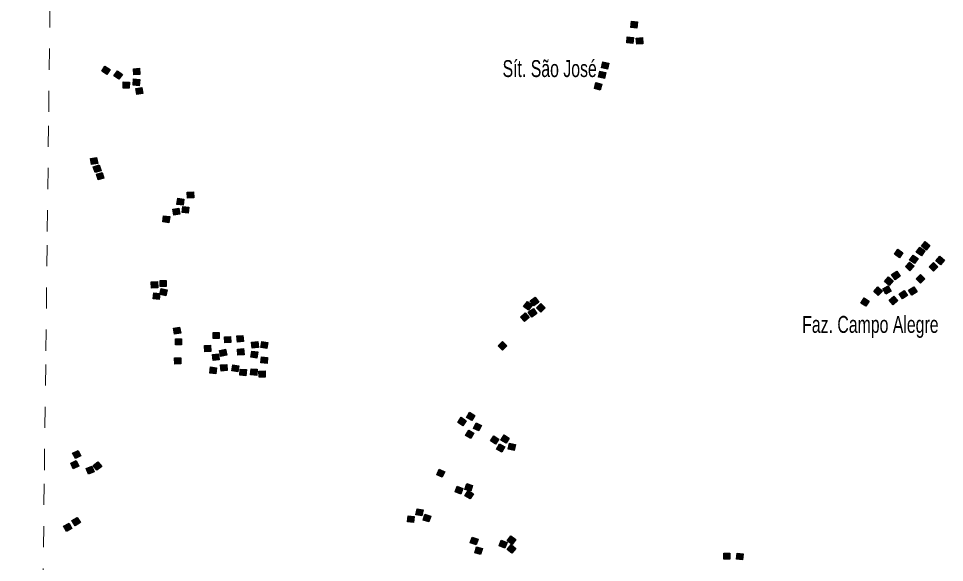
# Model space of a CAD drawing. Extents: x 679 to 705, y 7427.4 to 7455.4.
# Drawn here: x 679.037 to 683.416, y 7437.424 to 7439.999 of the extents above; entities that cross this region are included whole.
import ezdxf

# ---------------------------------------------------------------- set-up
doc = ezdxf.new("R2010")
doc.units = 0
doc.header["$LTSCALE"] = 0.032
doc.linetypes.add('SHORT_DASHED', pattern=[2.7, 1.5, -1.2])
doc.layers.add('2', color=7, linetype='Continuous', lineweight=25)
doc.layers.add('58', color=7, linetype='SHORT_DASHED', lineweight=13)
doc.layers.add('61', color=7, linetype='Continuous')

msp = doc.modelspace()

# ---------------------------------------------------------------- hatches: boundary and pattern name
at = {"layer": '2'}
for points in [[(681.9643, 7439.9827), (681.9609, 7439.9539), (681.9321, 7439.9572), (681.9355, 7439.986)], [(681.9448, 7439.9097), (681.9423, 7439.8808), (681.9134, 7439.8833), (681.9159, 7439.9122)], [(681.9873, 7439.9087), (681.9893, 7439.8797), (681.9604, 7439.8777), (681.9583, 7439.9066)], [(681.8286, 7439.7877), (681.8217, 7439.7595), (681.7935, 7439.7664), (681.8004, 7439.7945)], [(679.4463, 7439.7739), (679.4707, 7439.7582), (679.455, 7439.7338), (679.4306, 7439.7495)], [(679.5049, 7439.7518), (679.5283, 7439.7347), (679.5111, 7439.7113), (679.4877, 7439.7284)], [(679.61, 7439.7633), (679.6118, 7439.7344), (679.5828, 7439.7327), (679.5811, 7439.7616)], [(681.8141, 7439.7432), (681.8076, 7439.715), (681.7793, 7439.7214), (681.7858, 7439.7497)], [(679.5618, 7439.6984), (679.5611, 7439.6694), (679.5321, 7439.6701), (679.5328, 7439.6991)], [(679.6107, 7439.71), (679.6077, 7439.6812), (679.5788, 7439.6842), (679.5818, 7439.713)], [(681.7951, 7439.6888), (681.7883, 7439.6606), (681.7601, 7439.6674), (681.7669, 7439.6956)], [(679.6205, 7439.6731), (679.625, 7439.6444), (679.5964, 7439.6399), (679.5918, 7439.6686)], [(679.4064, 7439.3415), (679.4117, 7439.313), (679.3832, 7439.3077), (679.3779, 7439.3362)], [(679.4184, 7439.3062), (679.4276, 7439.2786), (679.4001, 7439.2695), (679.3909, 7439.297)], [(679.4337, 7439.2706), (679.4414, 7439.2427), (679.4135, 7439.2349), (679.4057, 7439.2628)], [(679.8645, 7439.1788), (679.8659, 7439.1498), (679.8369, 7439.1484), (679.8355, 7439.1774)], [(679.8189, 7439.1445), (679.8154, 7439.1157), (679.7866, 7439.1192), (679.7901, 7439.148)], [(679.7959, 7439.1019), (679.8004, 7439.0732), (679.7717, 7439.0688), (679.7672, 7439.0974)], [(679.8427, 7439.1064), (679.8395, 7439.0776), (679.8107, 7439.0808), (679.8139, 7439.1096)], [(679.7522, 7439.0613), (679.7482, 7439.0326), (679.7194, 7439.0366), (679.7234, 7439.0653)], [(683.2993, 7438.9164), (683.323, 7438.8997), (683.3064, 7438.876), (683.2826, 7438.8927)], [(683.3246, 7438.9437), (683.3471, 7438.9253), (683.3287, 7438.9029), (683.3063, 7438.9213)], [(683.1958, 7438.9068), (683.2194, 7438.89), (683.2026, 7438.8664), (683.179, 7438.8832)], [(683.2675, 7438.8797), (683.2912, 7438.863), (683.2744, 7438.8393), (683.2507, 7438.856)], [(683.3937, 7438.8736), (683.4157, 7438.8546), (683.3967, 7438.8327), (683.3748, 7438.8516)], [(683.251, 7438.8465), (683.2722, 7438.8267), (683.2524, 7438.8055), (683.2312, 7438.8253)], [(683.3632, 7438.8449), (683.3837, 7438.8244), (683.3632, 7438.8039), (683.3427, 7438.8244)], [(683.151, 7438.7762), (683.1733, 7438.7576), (683.1547, 7438.7354), (683.1325, 7438.7539)], [(683.1898, 7438.8032), (683.2062, 7438.7793), (683.1823, 7438.7628), (683.1659, 7438.7867)], [(683.3027, 7438.7875), (683.3232, 7438.767), (683.3026, 7438.7465), (683.2821, 7438.767)], [(679.694, 7438.754), (679.6955, 7438.725), (679.6665, 7438.7235), (679.6651, 7438.7525)], [(679.7362, 7438.7597), (679.7362, 7438.7307), (679.7072, 7438.7307), (679.7072, 7438.7597)], [(683.15, 7438.7342), (683.1643, 7438.709), (683.1391, 7438.6947), (683.1247, 7438.7199)], [(679.7058, 7438.6974), (679.7025, 7438.6686), (679.6737, 7438.6719), (679.677, 7438.7007)], [(679.7405, 7438.7149), (679.7341, 7438.6866), (679.7058, 7438.693), (679.7123, 7438.7213)], [(683.101, 7438.7284), (683.1223, 7438.7087), (683.1025, 7438.6874), (683.0813, 7438.7072)], [(683.225, 7438.7122), (683.2413, 7438.6882), (683.2173, 7438.6719), (683.201, 7438.6959)], [(683.27, 7438.7297), (683.2858, 7438.7054), (683.2615, 7438.6896), (683.2457, 7438.7138)], [(681.4434, 7438.6597), (681.4663, 7438.642), (681.4487, 7438.619), (681.4257, 7438.6367)], [(681.4806, 7438.6804), (681.4979, 7438.6571), (681.4745, 7438.6399), (681.4573, 7438.6632)], [(681.5065, 7438.6503), (681.527, 7438.6298), (681.5064, 7438.6093), (681.4859, 7438.6298)], [(683.0352, 7438.6768), (683.0598, 7438.6615), (683.0444, 7438.6369), (683.0198, 7438.6523)], [(683.1762, 7438.6854), (683.1955, 7438.6637), (683.1738, 7438.6444), (683.1546, 7438.6661)], [(681.4325, 7438.6056), (681.4519, 7438.584), (681.4304, 7438.5646), (681.411, 7438.5862)], [(681.4718, 7438.6261), (681.4881, 7438.6021), (681.4642, 7438.5858), (681.4478, 7438.6097)], [(679.7988, 7438.5385), (679.8041, 7438.51), (679.7756, 7438.5047), (679.7703, 7438.5333)], [(679.9863, 7438.5128), (679.9863, 7438.4838), (679.9573, 7438.4838), (679.9573, 7438.5128)], [(679.808, 7438.4837), (679.808, 7438.4547), (679.779, 7438.4547), (679.779, 7438.4837)], [(680.0401, 7438.4938), (680.0414, 7438.4649), (680.0124, 7438.4635), (680.0111, 7438.4925)], [(680.0984, 7438.4992), (680.101, 7438.4703), (680.0722, 7438.4677), (680.0695, 7438.4966)], [(680.1685, 7438.4707), (680.1717, 7438.4419), (680.1428, 7438.4387), (680.1396, 7438.4675)], [(680.2168, 7438.4653), (680.2121, 7438.4367), (680.1835, 7438.4415), (680.1882, 7438.4701)], [(681.3265, 7438.47), (681.3468, 7438.4493), (681.326, 7438.429), (681.3058, 7438.4497)], [(679.9459, 7438.4524), (679.9474, 7438.4235), (679.9185, 7438.422), (679.917, 7438.4509)], [(680.0167, 7438.4336), (680.023, 7438.4053), (679.9947, 7438.399), (679.9884, 7438.4273)], [(680.1019, 7438.4367), (680.104, 7438.4078), (680.075, 7438.4057), (680.073, 7438.4347)], [(679.8045, 7438.3929), (679.805, 7438.3639), (679.776, 7438.3635), (679.7755, 7438.3925)], [(679.9831, 7438.4127), (679.9863, 7438.3839), (679.9575, 7438.3806), (679.9543, 7438.4095)], [(680.1686, 7438.4209), (680.1643, 7438.3922), (680.1356, 7438.3965), (680.1399, 7438.4252)], [(680.2152, 7438.3953), (680.2127, 7438.3664), (680.1838, 7438.3689), (680.1863, 7438.3978)], [(679.9738, 7438.3463), (679.9702, 7438.3175), (679.9414, 7438.3211), (679.945, 7438.3499)], [(680.0221, 7438.3618), (680.0243, 7438.3329), (679.9954, 7438.3307), (679.9932, 7438.3596)], [(680.0795, 7438.3552), (680.0748, 7438.3266), (680.0461, 7438.3314), (680.0509, 7438.36)], [(680.115, 7438.3375), (680.113, 7438.3086), (680.0841, 7438.3106), (680.0861, 7438.3395)], [(680.1659, 7438.3389), (680.1638, 7438.3099), (680.1349, 7438.312), (680.1369, 7438.3409)], [(680.203, 7438.3309), (680.2038, 7438.3019), (680.1748, 7438.3011), (680.174, 7438.3301)], [(681.1704, 7438.1354), (681.1954, 7438.1207), (681.1808, 7438.0957), (681.1557, 7438.1103)], [(681.1302, 7438.1117), (681.1542, 7438.0955), (681.1379, 7438.0715), (681.1139, 7438.0877)], [(681.2006, 7438.0854), (681.2268, 7438.0731), (681.2145, 7438.0468), (681.1883, 7438.0591)], [(681.166, 7438.0509), (681.1907, 7438.0357), (681.1755, 7438.011), (681.1508, 7438.0262)], [(681.2848, 7438.024), (681.3088, 7438.0078), (681.2926, 7437.9837), (681.2686, 7438)], [(681.3334, 7438.0286), (681.3581, 7438.0134), (681.343, 7437.9887), (681.3182, 7438.0038)], [(681.3594, 7437.9893), (681.3877, 7437.983), (681.3814, 7437.9547), (681.3531, 7437.961)], [(679.319, 7437.955), (679.3325, 7437.9293), (679.3069, 7437.9158), (679.2934, 7437.9415)], [(681.312, 7437.9853), (681.3372, 7437.9711), (681.323, 7437.9458), (681.2977, 7437.9601)], [(679.3106, 7437.9067), (679.3225, 7437.8803), (679.296, 7437.8684), (679.2842, 7437.8949)], [(679.4129, 7437.9014), (679.4307, 7437.8785), (679.4078, 7437.8607), (679.39, 7437.8836)], [(679.3845, 7437.881), (679.3956, 7437.8542), (679.3688, 7437.8431), (679.3577, 7437.8699)], [(681.0533, 7437.8541), (681.0413, 7437.8277), (681.0149, 7437.8397), (681.0269, 7437.8661)], [(681.139, 7437.7752), (681.1283, 7437.7483), (681.1013, 7437.759), (681.1121, 7437.786)], [(681.1846, 7437.7893), (681.1759, 7437.7616), (681.1483, 7437.7703), (681.157, 7437.798)], [(681.188, 7437.7496), (681.1726, 7437.725), (681.148, 7437.7404), (681.1634, 7437.765)], [(679.3146, 7437.6378), (679.3297, 7437.6131), (679.305, 7437.598), (679.2899, 7437.6227)], [(680.9086, 7437.6421), (680.9047, 7437.6133), (680.876, 7437.6172), (680.8798, 7437.6459)], [(680.9507, 7437.6731), (680.9452, 7437.6446), (680.9167, 7437.6501), (680.9222, 7437.6785)], [(680.9869, 7437.6441), (680.9783, 7437.6164), (680.9506, 7437.6251), (680.9592, 7437.6528)], [(679.2761, 7437.6103), (679.2894, 7437.5846), (679.2637, 7437.5713), (679.2503, 7437.597)], [(681.3648, 7437.5503), (681.3886, 7437.5338), (681.372, 7437.51), (681.3482, 7437.5265)], [(681.2104, 7437.535), (681.2008, 7437.5077), (681.1735, 7437.5173), (681.1831, 7437.5446)], [(681.3202, 7437.5296), (681.3474, 7437.5197), (681.3375, 7437.4924), (681.3103, 7437.5024)], [(681.3661, 7437.5091), (681.3887, 7437.4909), (681.3706, 7437.4683), (681.3479, 7437.4864)], [(681.2026, 7437.4987), (681.2305, 7437.4907), (681.2225, 7437.4628), (681.1946, 7437.4708)], [(682.4007, 7437.4686), (682.4007, 7437.4396), (682.3717, 7437.4396), (682.3717, 7437.4686)], [(682.4645, 7437.4653), (682.461, 7437.4365), (682.4322, 7437.44), (682.4357, 7437.4688)]]:
    msp.add_hatch(color=256, dxfattribs=at).paths.add_polyline_path(points)

# ---------------------------------------------------------------- linework, layer by layer
for points in [[(681.9643, 7439.9827), (681.9609, 7439.9539), (681.9321, 7439.9572), (681.9355, 7439.986)], [(681.9448, 7439.9097), (681.9423, 7439.8808), (681.9134, 7439.8833), (681.9159, 7439.9122)], [(681.9873, 7439.9087), (681.9893, 7439.8797), (681.9604, 7439.8777), (681.9583, 7439.9066)], [(681.8286, 7439.7877), (681.8217, 7439.7595), (681.7935, 7439.7664), (681.8004, 7439.7945)], [(679.4463, 7439.7739), (679.4707, 7439.7582), (679.455, 7439.7338), (679.4306, 7439.7495)], [(679.5049, 7439.7518), (679.5283, 7439.7347), (679.5111, 7439.7113), (679.4877, 7439.7284)], [(679.61, 7439.7633), (679.6118, 7439.7344), (679.5828, 7439.7327), (679.5811, 7439.7616)], [(681.8141, 7439.7432), (681.8076, 7439.715), (681.7793, 7439.7214), (681.7858, 7439.7497)], [(679.5618, 7439.6984), (679.5611, 7439.6694), (679.5321, 7439.6701), (679.5328, 7439.6991)], [(679.6107, 7439.71), (679.6077, 7439.6812), (679.5788, 7439.6842), (679.5818, 7439.713)], [(681.7951, 7439.6888), (681.7883, 7439.6606), (681.7601, 7439.6674), (681.7669, 7439.6956)], [(679.6205, 7439.6731), (679.625, 7439.6444), (679.5964, 7439.6399), (679.5918, 7439.6686)], [(679.4064, 7439.3415), (679.4117, 7439.313), (679.3832, 7439.3077), (679.3779, 7439.3362)], [(679.4184, 7439.3062), (679.4276, 7439.2786), (679.4001, 7439.2695), (679.3909, 7439.297)], [(679.4337, 7439.2706), (679.4414, 7439.2427), (679.4135, 7439.2349), (679.4057, 7439.2628)], [(679.8645, 7439.1788), (679.8659, 7439.1498), (679.8369, 7439.1484), (679.8355, 7439.1774)], [(679.8189, 7439.1445), (679.8154, 7439.1157), (679.7866, 7439.1192), (679.7901, 7439.148)], [(679.7959, 7439.1019), (679.8004, 7439.0732), (679.7717, 7439.0688), (679.7672, 7439.0974)], [(679.8427, 7439.1064), (679.8395, 7439.0776), (679.8107, 7439.0808), (679.8139, 7439.1096)], [(679.7522, 7439.0613), (679.7482, 7439.0326), (679.7194, 7439.0366), (679.7234, 7439.0653)], [(683.2993, 7438.9164), (683.323, 7438.8997), (683.3064, 7438.876), (683.2826, 7438.8927)], [(683.3246, 7438.9437), (683.3471, 7438.9253), (683.3287, 7438.9029), (683.3063, 7438.9213)], [(683.1958, 7438.9068), (683.2194, 7438.89), (683.2026, 7438.8664), (683.179, 7438.8832)], [(683.2675, 7438.8797), (683.2912, 7438.863), (683.2744, 7438.8393), (683.2507, 7438.856)], [(683.3937, 7438.8736), (683.4157, 7438.8546), (683.3967, 7438.8327), (683.3748, 7438.8516)], [(683.251, 7438.8465), (683.2722, 7438.8267), (683.2524, 7438.8055), (683.2312, 7438.8253)], [(683.3632, 7438.8449), (683.3837, 7438.8244), (683.3632, 7438.8039), (683.3427, 7438.8244)], [(683.151, 7438.7762), (683.1733, 7438.7576), (683.1547, 7438.7354), (683.1325, 7438.7539)], [(683.1898, 7438.8032), (683.2062, 7438.7793), (683.1823, 7438.7628), (683.1659, 7438.7867)], [(683.3027, 7438.7875), (683.3232, 7438.767), (683.3026, 7438.7465), (683.2821, 7438.767)], [(679.694, 7438.754), (679.6955, 7438.725), (679.6665, 7438.7235), (679.6651, 7438.7525)], [(679.7362, 7438.7597), (679.7362, 7438.7307), (679.7072, 7438.7307), (679.7072, 7438.7597)], [(683.15, 7438.7342), (683.1643, 7438.709), (683.1391, 7438.6947), (683.1247, 7438.7199)], [(679.7058, 7438.6974), (679.7025, 7438.6686), (679.6737, 7438.6719), (679.677, 7438.7007)], [(679.7405, 7438.7149), (679.7341, 7438.6866), (679.7058, 7438.693), (679.7123, 7438.7213)], [(683.101, 7438.7284), (683.1223, 7438.7087), (683.1025, 7438.6874), (683.0813, 7438.7072)], [(683.225, 7438.7122), (683.2413, 7438.6882), (683.2173, 7438.6719), (683.201, 7438.6959)], [(683.27, 7438.7297), (683.2858, 7438.7054), (683.2615, 7438.6896), (683.2457, 7438.7138)], [(681.4434, 7438.6597), (681.4663, 7438.642), (681.4487, 7438.619), (681.4257, 7438.6367)], [(681.4806, 7438.6804), (681.4979, 7438.6571), (681.4745, 7438.6399), (681.4573, 7438.6632)], [(681.5065, 7438.6503), (681.527, 7438.6298), (681.5064, 7438.6093), (681.4859, 7438.6298)], [(683.0352, 7438.6768), (683.0598, 7438.6615), (683.0444, 7438.6369), (683.0198, 7438.6523)], [(683.1762, 7438.6854), (683.1955, 7438.6637), (683.1738, 7438.6444), (683.1546, 7438.6661)], [(681.4325, 7438.6056), (681.4519, 7438.584), (681.4304, 7438.5646), (681.411, 7438.5862)], [(681.4718, 7438.6261), (681.4881, 7438.6021), (681.4642, 7438.5858), (681.4478, 7438.6097)], [(679.7988, 7438.5385), (679.8041, 7438.51), (679.7756, 7438.5047), (679.7703, 7438.5333)], [(679.9863, 7438.5128), (679.9863, 7438.4838), (679.9573, 7438.4838), (679.9573, 7438.5128)], [(679.808, 7438.4837), (679.808, 7438.4547), (679.779, 7438.4547), (679.779, 7438.4837)], [(680.0401, 7438.4938), (680.0414, 7438.4649), (680.0124, 7438.4635), (680.0111, 7438.4925)], [(680.0984, 7438.4992), (680.101, 7438.4703), (680.0722, 7438.4677), (680.0695, 7438.4966)], [(680.1685, 7438.4707), (680.1717, 7438.4419), (680.1428, 7438.4387), (680.1396, 7438.4675)], [(680.2168, 7438.4653), (680.2121, 7438.4367), (680.1835, 7438.4415), (680.1882, 7438.4701)], [(681.3265, 7438.47), (681.3468, 7438.4493), (681.326, 7438.429), (681.3058, 7438.4497)], [(679.9459, 7438.4524), (679.9474, 7438.4235), (679.9185, 7438.422), (679.917, 7438.4509)], [(680.0167, 7438.4336), (680.023, 7438.4053), (679.9947, 7438.399), (679.9884, 7438.4273)], [(680.1019, 7438.4367), (680.104, 7438.4078), (680.075, 7438.4057), (680.073, 7438.4347)], [(679.8045, 7438.3929), (679.805, 7438.3639), (679.776, 7438.3635), (679.7755, 7438.3925)], [(679.9831, 7438.4127), (679.9863, 7438.3839), (679.9575, 7438.3806), (679.9543, 7438.4095)], [(680.1686, 7438.4209), (680.1643, 7438.3922), (680.1356, 7438.3965), (680.1399, 7438.4252)], [(680.2152, 7438.3953), (680.2127, 7438.3664), (680.1838, 7438.3689), (680.1863, 7438.3978)], [(679.9738, 7438.3463), (679.9702, 7438.3175), (679.9414, 7438.3211), (679.945, 7438.3499)], [(680.0221, 7438.3618), (680.0243, 7438.3329), (679.9954, 7438.3307), (679.9932, 7438.3596)], [(680.0795, 7438.3552), (680.0748, 7438.3266), (680.0461, 7438.3314), (680.0509, 7438.36)], [(680.115, 7438.3375), (680.113, 7438.3086), (680.0841, 7438.3106), (680.0861, 7438.3395)], [(680.1659, 7438.3389), (680.1638, 7438.3099), (680.1349, 7438.312), (680.1369, 7438.3409)], [(680.203, 7438.3309), (680.2038, 7438.3019), (680.1748, 7438.3011), (680.174, 7438.3301)], [(681.1704, 7438.1354), (681.1954, 7438.1207), (681.1808, 7438.0957), (681.1557, 7438.1103)], [(681.1302, 7438.1117), (681.1542, 7438.0955), (681.1379, 7438.0715), (681.1139, 7438.0877)], [(681.2006, 7438.0854), (681.2268, 7438.0731), (681.2145, 7438.0468), (681.1883, 7438.0591)], [(681.166, 7438.0509), (681.1907, 7438.0357), (681.1755, 7438.011), (681.1508, 7438.0262)], [(681.2848, 7438.024), (681.3088, 7438.0078), (681.2926, 7437.9837), (681.2686, 7438)], [(681.3334, 7438.0286), (681.3581, 7438.0134), (681.343, 7437.9887), (681.3182, 7438.0038)], [(681.3594, 7437.9893), (681.3877, 7437.983), (681.3814, 7437.9547), (681.3531, 7437.961)], [(679.319, 7437.955), (679.3325, 7437.9293), (679.3069, 7437.9158), (679.2934, 7437.9415)], [(681.312, 7437.9853), (681.3372, 7437.9711), (681.323, 7437.9458), (681.2977, 7437.9601)], [(679.3106, 7437.9067), (679.3225, 7437.8803), (679.296, 7437.8684), (679.2842, 7437.8949)], [(679.4129, 7437.9014), (679.4307, 7437.8785), (679.4078, 7437.8607), (679.39, 7437.8836)], [(679.3845, 7437.881), (679.3956, 7437.8542), (679.3688, 7437.8431), (679.3577, 7437.8699)], [(681.0533, 7437.8541), (681.0413, 7437.8277), (681.0149, 7437.8397), (681.0269, 7437.8661)], [(681.139, 7437.7752), (681.1283, 7437.7483), (681.1013, 7437.759), (681.1121, 7437.786)], [(681.1846, 7437.7893), (681.1759, 7437.7616), (681.1483, 7437.7703), (681.157, 7437.798)], [(681.188, 7437.7496), (681.1726, 7437.725), (681.148, 7437.7404), (681.1634, 7437.765)], [(679.3146, 7437.6378), (679.3297, 7437.6131), (679.305, 7437.598), (679.2899, 7437.6227)], [(680.9086, 7437.6421), (680.9047, 7437.6133), (680.876, 7437.6172), (680.8798, 7437.6459)], [(680.9507, 7437.6731), (680.9452, 7437.6446), (680.9167, 7437.6501), (680.9222, 7437.6785)], [(680.9869, 7437.6441), (680.9783, 7437.6164), (680.9506, 7437.6251), (680.9592, 7437.6528)], [(679.2761, 7437.6103), (679.2894, 7437.5846), (679.2637, 7437.5713), (679.2503, 7437.597)], [(681.3648, 7437.5503), (681.3886, 7437.5338), (681.372, 7437.51), (681.3482, 7437.5265)], [(681.2104, 7437.535), (681.2008, 7437.5077), (681.1735, 7437.5173), (681.1831, 7437.5446)], [(681.3202, 7437.5296), (681.3474, 7437.5197), (681.3375, 7437.4924), (681.3103, 7437.5024)], [(681.3661, 7437.5091), (681.3887, 7437.4909), (681.3706, 7437.4683), (681.3479, 7437.4864)], [(681.2026, 7437.4987), (681.2305, 7437.4907), (681.2225, 7437.4628), (681.1946, 7437.4708)], [(682.4007, 7437.4686), (682.4007, 7437.4396), (682.3717, 7437.4396), (682.3717, 7437.4686)], [(682.4645, 7437.4653), (682.461, 7437.4365), (682.4322, 7437.44), (682.4357, 7437.4688)]]:
    msp.add_lwpolyline(points, close=True, dxfattribs=at)
at = {"layer": '58'}
msp.add_lwpolyline([(679.0374, 7427.6915), (679.0442, 7428.2565), (679.051, 7428.8215), (679.0578, 7429.3865), (679.0646, 7429.9515), (679.0714, 7430.5166), (679.0782, 7431.0816), (679.085, 7431.6466), (679.0918, 7432.2116), (679.0986, 7432.7766), (679.1054, 7433.3416), (679.1122, 7433.9066), (679.119, 7434.4716), (679.1258, 7435.0366), (679.1326, 7435.6016), (679.1394, 7436.1666), (679.1462, 7436.7316), (679.153, 7437.2966), (679.1598, 7437.8616), (679.1666, 7438.4266), (679.1734, 7438.9916), (679.1802, 7439.5566), (679.1869, 7440.1216)], dxfattribs=at)

# ---------------------------------------------------------------- texts
at = {"layer": '61', "width": 0.7}
for s, p in [('Sít. São José', (681.3262, 7439.7221)), ('Faz. Campo Alegre', (682.7427, 7438.5112))]:
    msp.add_text(s, height=0.08, dxfattribs=at).set_placement(p)

doc.saveas('drawing.dxf')
